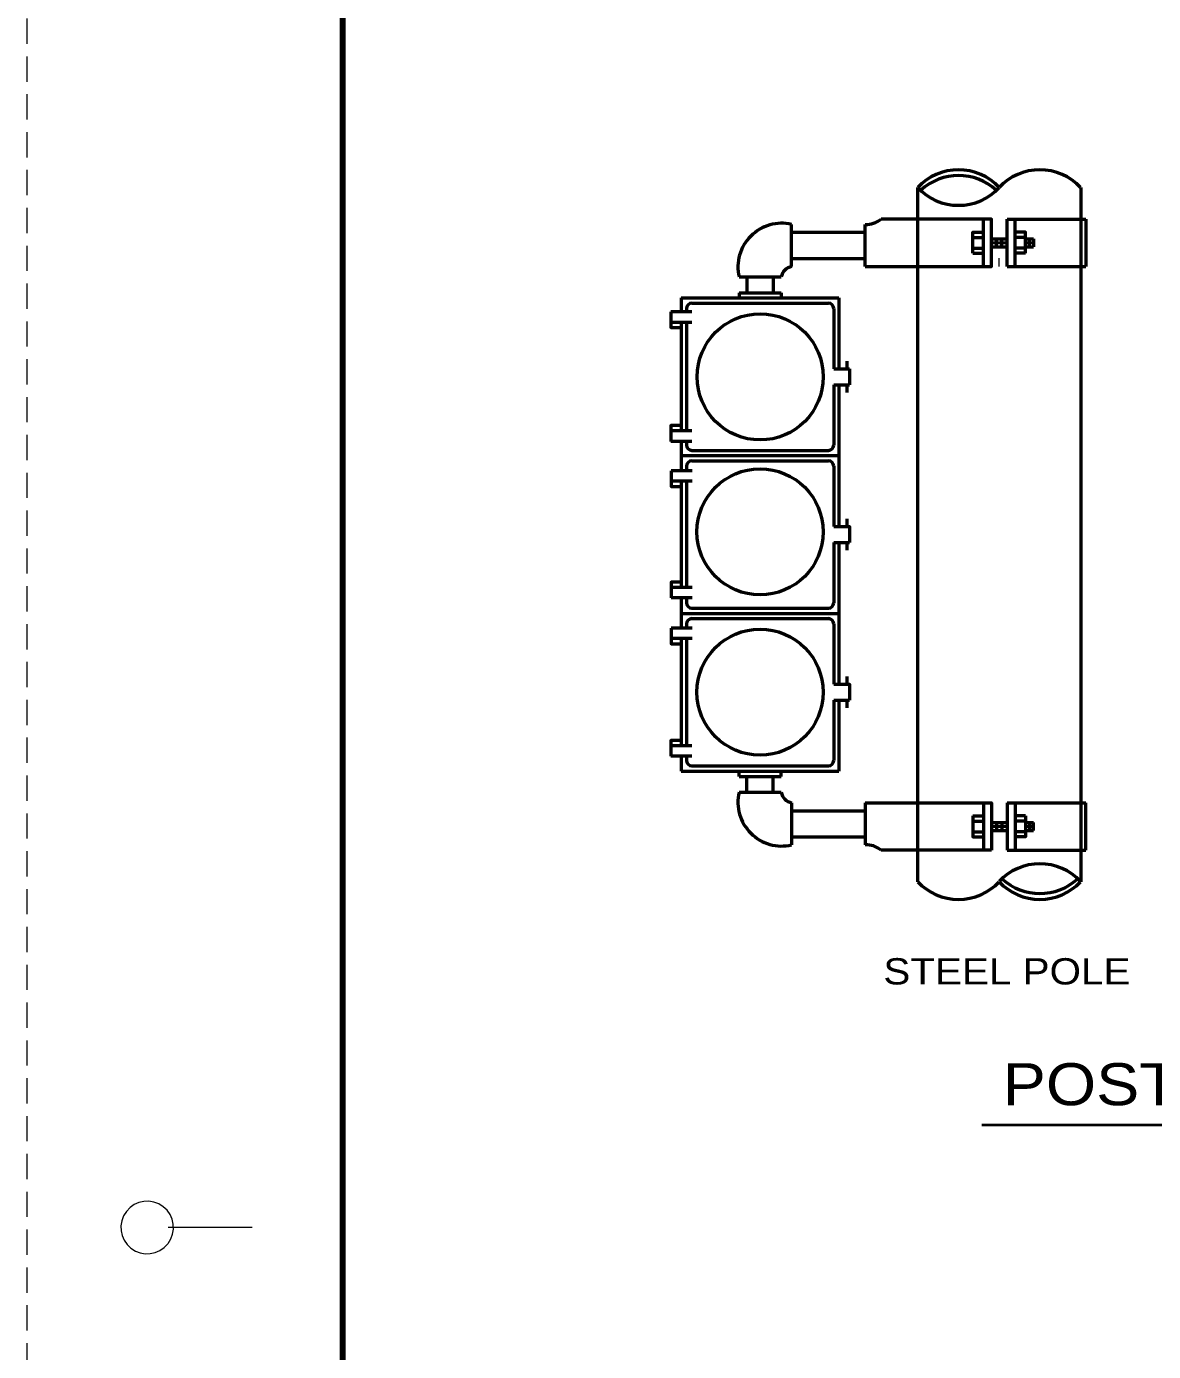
# Model space of a CAD drawing. Extents: x -286 to 394, y -156 to 284.
# Drawn here: x -286.4 to -179.2, y -29.5 to 96.5 of the extents above; entities that cross this region are included whole.
import ezdxf
from ezdxf.enums import TextEntityAlignment as Align

# ---------------------------------------------------------------- set-up
doc = ezdxf.new("R2010")
doc.units = 0
doc.header["$LTSCALE"] = 0.8
doc.linetypes.add('MEDIUM_DASHED', pattern=[4.5, 3, -1.5])
doc.layers.add('1', color=7, linetype='Continuous', lineweight=53)
doc.layers.add('61', color=7, linetype='Continuous', lineweight=35)

msp = doc.modelspace()

# ---------------------------------------------------------------- linework, layer by layer
at = {"layer": '1', "linetype": 'MEDIUM_DASHED', "lineweight": 13}
msp.add_line((-286.3491, 284.4627), (-286.4091, -155.5772), dxfattribs=at)
at = {"layer": '1'}
for p, q in [((-201.6205, 15.1619), (-201.6205, 81.1877)), ((-186.1205, 81.1877), (-186.1205, 15.1619)), ((-195.3705, 73.6877), (-195.3705, 78.1877)), ((-193.1205, 73.6877), (-193.1205, 78.1877)), ((-193.1205, 78.1877), (-185.6205, 78.1877)), ((-192.3705, 73.6877), (-192.3705, 78.1877)), ((-185.6205, 78.1877), (-185.6205, 73.6877)), ((-213.6205, 73.6877), (-213.6205, 77.6877)), ((-213.6205, 76.9377), (-206.6205, 76.9377)), ((-206.6205, 73.6877), (-206.6205, 77.6877)), ((-196.3705, 76.4377), (-195.3705, 76.4377)), ((-194.6205, 76.3127), (-193.1205, 76.3127)), ((-194.3705, 75.8127), (-194.3705, 76.0627)), ((-194.1205, 75.5627), (-194.1205, 76.3127)), ((-193.8705, 75.8127), (-193.8705, 76.0627)), ((-193.6205, 75.5627), (-193.6205, 76.3127)), ((-193.3705, 75.8127), (-193.3705, 76.0627)), ((-191.3735, 76.4377), (-192.3735, 76.4377)), ((-191.186, 76.0627), (-191.186, 75.8127)), ((-190.9985, 75.5627), (-190.9985, 76.3127)), ((-190.811, 76.0627), (-190.811, 75.8127)), ((-190.6235, 76.3127), (-190.6235, 75.5627)), ((-213.6205, 74.4377), (-206.6205, 74.4377)), ((-196.3705, 75.4377), (-195.3705, 75.4377)), ((-196.3705, 74.9377), (-195.3705, 74.9377)), ((-194.6205, 75.5627), (-193.1205, 75.5627)), ((-191.3735, 75.4377), (-192.3735, 75.4377)), ((-191.3735, 74.9377), (-192.3735, 74.9377)), ((-191.3735, 75.5627), (-190.6235, 75.5627)), ((-193.1205, 73.6877), (-185.6205, 73.6877)), ((-218.6205, 72.6877), (-214.6205, 72.6877)), ((-217.8705, 72.6877), (-217.8705, 71.1877)), ((-215.3705, 72.6877), (-215.3705, 71.1877)), ((-224.1205, 70.6877), (-209.1205, 70.6877)), ((-224.1205, 70.6877), (-224.1205, 69.3678)), ((-218.6205, 71.1877), (-214.6205, 71.1877)), ((-218.6205, 71.1877), (-218.6205, 70.6877)), ((-214.6205, 71.1877), (-214.6205, 70.6877)), ((-209.1205, 70.6877), (-209.1205, 63.9378)), ((-223.1205, 69.3678), (-225.1205, 69.3678)), ((-223.6205, 69.6877), (-223.6205, 69.3678)), ((-223.1205, 70.1877), (-210.1205, 70.1877)), ((-209.6205, 69.6877), (-209.6205, 63.9378)), ((-223.1205, 68.3678), (-225.1205, 68.3678)), ((-224.1205, 68.3678), (-224.1205, 58.0468)), ((-223.6205, 68.3678), (-223.6205, 58.0468)), ((-208.3705, 64.6877), (-208.3705, 63.9378)), ((-209.6205, 63.9378), (-208.1205, 63.9378)), ((-208.1205, 63.9378), (-208.1205, 62.4378)), ((-209.6205, 62.4378), (-209.6205, 56.6878)), ((-209.6205, 62.4378), (-208.1205, 62.4378)), ((-209.1205, 62.4378), (-209.1205, 48.9378)), ((-208.3705, 62.4378), (-208.3705, 61.6878)), ((-223.1205, 58.0468), (-225.1205, 58.0468)), ((-223.1205, 57.0468), (-225.1205, 57.0468)), ((-224.1205, 57.0468), (-224.1205, 54.2587)), ((-223.6205, 57.0468), (-223.6205, 56.6878)), ((-224.1205, 55.6878), (-209.1205, 55.6878)), ((-223.1205, 56.1878), (-210.1205, 56.1878)), ((-223.0789, 54.2587), (-225.0789, 54.2587)), ((-223.6205, 54.6878), (-223.6205, 54.2587)), ((-223.1205, 55.1878), (-210.1205, 55.1878)), ((-209.6205, 54.6878), (-209.6205, 48.9378)), ((-223.0789, 53.2587), (-225.0789, 53.2587)), ((-224.1205, 53.2587), (-224.1205, 43.1597)), ((-223.6205, 53.2587), (-223.6205, 43.1597)), ((-208.3705, 49.6878), (-208.3705, 48.9378)), ((-209.6205, 47.4378), (-208.1205, 47.4378)), ((-209.6205, 47.4378), (-209.6205, 41.6878)), ((-209.1205, 47.4378), (-209.1205, 33.9378)), ((-208.3705, 47.4378), (-208.3705, 46.6878)), ((-223.0789, 43.1597), (-225.0789, 43.1597)), ((-223.0789, 42.1597), (-225.0789, 42.1597)), ((-224.1205, 42.1597), (-224.1205, 39.2854)), ((-223.6205, 42.1597), (-223.6205, 41.6878)), ((-224.1205, 40.6878), (-209.1205, 40.6878)), ((-223.1205, 41.1878), (-210.1205, 41.1878)), ((-223.0956, 39.2854), (-225.0956, 39.2854)), ((-223.6205, 39.6878), (-223.6205, 39.2854)), ((-223.1205, 40.1878), (-210.1205, 40.1878)), ((-209.6205, 39.6878), (-209.6205, 33.9378)), ((-223.0956, 38.2854), (-225.0956, 38.2854)), ((-224.1205, 38.2854), (-224.1205, 28.0879)), ((-223.6205, 38.2854), (-223.6205, 28.0879)), ((-208.3705, 34.6878), (-208.3705, 33.9378)), ((-209.6205, 32.4378), (-208.1205, 32.4378)), ((-209.6205, 32.4378), (-209.6205, 26.6877)), ((-209.1205, 32.4378), (-209.1205, 25.6877)), ((-208.3705, 32.4378), (-208.3705, 31.6877)), ((-223.1219, 28.0879), (-225.1219, 28.0879)), ((-223.1219, 27.0879), (-225.1219, 27.0879)), ((-224.1205, 27.0879), (-224.1205, 25.6877)), ((-223.6205, 27.0879), (-223.6205, 26.6877)), ((-224.1205, 25.6877), (-209.1205, 25.6877)), ((-223.1205, 26.1877), (-210.1205, 26.1877)), ((-218.6205, 25.1619), (-218.6205, 25.6619)), ((-214.6205, 25.1619), (-214.6205, 25.6619)), ((-218.6205, 25.1619), (-214.6205, 25.1619)), ((-217.8705, 23.6619), (-217.8705, 25.1619)), ((-215.3705, 23.6619), (-215.3705, 25.1619)), ((-218.6205, 23.6619), (-214.6205, 23.6619)), ((-213.6205, 22.6619), (-213.6205, 18.6619)), ((-213.6205, 21.9119), (-206.6205, 21.9119)), ((-206.6205, 22.6619), (-206.6205, 18.6619)), ((-195.3705, 22.6619), (-195.3705, 18.1619)), ((-193.1205, 22.6619), (-193.1205, 18.1619)), ((-193.1205, 22.6619), (-185.6205, 22.6619)), ((-192.3705, 22.6619), (-192.3705, 18.1619)), ((-185.6205, 18.1619), (-185.6205, 22.6619)), ((-196.3705, 21.4119), (-195.3705, 21.4119)), ((-196.3705, 20.9119), (-195.3705, 20.9119)), ((-194.6205, 20.7869), (-193.1205, 20.7869)), ((-194.3705, 20.5369), (-194.3705, 20.2869)), ((-194.1205, 20.7869), (-194.1205, 20.0369)), ((-193.8705, 20.5369), (-193.8705, 20.2869)), ((-193.6205, 20.7869), (-193.6205, 20.0369)), ((-193.3705, 20.5369), (-193.3705, 20.2869)), ((-191.3735, 21.4119), (-192.3735, 21.4119)), ((-191.3735, 20.9119), (-192.3735, 20.9119)), ((-191.3735, 20.7869), (-190.6235, 20.7869)), ((-191.186, 20.2869), (-191.186, 20.5369)), ((-190.9985, 20.7869), (-190.9985, 20.0369)), ((-190.811, 20.2869), (-190.811, 20.5369)), ((-190.6235, 20.0369), (-190.6235, 20.7869)), ((-213.6205, 19.4119), (-206.6205, 19.4119)), ((-196.3705, 19.9119), (-195.3705, 19.9119)), ((-194.6205, 20.0369), (-193.1205, 20.0369)), ((-191.3735, 19.9119), (-192.3735, 19.9119)), ((-191.3735, 20.0369), (-190.6235, 20.0369)), ((-194.6205, 18.1619), (-205.1205, 18.1619)), ((-193.1205, 18.1619), (-185.6205, 18.1619))]:
    msp.add_line(p, q, dxfattribs=at)
at = {"layer": '1', "lineweight": 13}
msp.add_line((-193.8705, 73.6877), (-193.8705, 74.4736), dxfattribs=at)
at = {"layer": '1', "lineweight": 40}
msp.add_line((-195.529, -7.9817), (-123.0741, -7.9817), dxfattribs=at)
at = {"layer": '1'}
for points in [[(-206.6205, 73.6877), (-194.6205, 73.6877), (-194.6205, 78.1877), (-205.1205, 78.1877)], [(-196.3705, 74.9377), (-196.3705, 76.9377), (-195.3705, 76.9377)], [(-191.3735, 74.9377), (-191.3735, 76.9377), (-192.3735, 76.9377)], [(-191.3735, 76.3127), (-190.9985, 76.3127), (-190.6235, 76.3127)], [(-225.1205, 69.3678), (-225.1205, 67.8678), (-224.1205, 67.8678)], [(-224.1205, 58.5468), (-225.1205, 58.5468), (-225.1205, 57.0468)], [(-225.0789, 54.2587), (-225.0789, 52.7587), (-224.0789, 52.7587)], [(-209.6205, 48.9378), (-208.1205, 48.9378), (-208.1205, 47.4378)], [(-224.0789, 43.6597), (-225.0789, 43.6597), (-225.0789, 42.1597)], [(-225.0956, 39.2854), (-225.0956, 37.7854), (-224.0956, 37.7854)], [(-209.6205, 33.9378), (-208.1205, 33.9378), (-208.1205, 32.4378)], [(-224.1219, 28.5879), (-225.1219, 28.5879), (-225.1219, 27.0879)], [(-206.6205, 22.6619), (-194.6205, 22.6619), (-194.6205, 18.1619)], [(-196.3705, 21.4119), (-196.3705, 19.4119), (-195.3705, 19.4119)], [(-191.3735, 21.4119), (-191.3735, 19.4119), (-192.3735, 19.4119)]]:
    msp.add_lwpolyline(points, dxfattribs=at)
for centre in [(-216.6142, 63.1818), (-216.6257, 48.4382), (-216.6261, 33.1901)]:
    msp.add_circle(centre, 6, dxfattribs=at)
for centre, radius, start, end in [((-197.7455, 77.5927), 5.2962, 42.97503, 137.02497), ((-197.7455, 77.0371), 5.2962, 47.11243, 132.88757), ((-190.0073, 77.5927), 5.2962, 42.97503, 137.02497), ((-197.7455, 84.7981), 5.2962, 222.97503, 317.02497), ((-206.4918, 79.8017), 2.1178, 266.51631, 310.35359), ((-214.565, 73.6322), 4.164, 76.89015, 193.10985), ((-213.337, 72.4042), 1.3145, 102.45679, 167.54321), ((-223.1205, 69.6877), 0.5, 90, 180), ((-210.1205, 69.6877), 0.5, 0, 90), ((-223.1205, 56.6878), 0.5, 180, 270), ((-210.1205, 56.6878), 0.5, 270, 0), ((-223.1205, 54.6878), 0.5, 90, 180), ((-210.1205, 54.6878), 0.5, 0, 90), ((-223.1205, 41.6878), 0.5, 180, 270), ((-210.1205, 41.6878), 0.5, 270, 0), ((-223.1205, 39.6878), 0.5, 90, 180), ((-210.1205, 39.6878), 0.5, 0, 90), ((-223.1205, 26.6877), 0.5, 180, 270), ((-210.1205, 26.6877), 0.5, 270, 0), ((-214.565, 22.7174), 4.164, 166.89015, 283.10985), ((-213.337, 23.9455), 1.3145, 192.45679, 257.54321), ((-206.4918, 16.548), 2.1178, 49.64641, 93.48369), ((-190.0073, 11.5669), 5.2962, 42.97503, 137.02497), ((-197.7455, 18.7723), 5.2962, 222.97503, 317.02497), ((-190.0073, 18.7723), 5.2962, 222.97503, 317.02497), ((-190.0073, 19.3279), 5.2962, 227.11243, 312.88757)]:
    msp.add_arc(centre, radius, start, end, dxfattribs=at)
at = {"layer": '61', "lineweight": 13}
msp.add_line((-272.9291, -17.7172), (-264.9291, -17.7172), dxfattribs=at)
at = {"layer": '61', "lineweight": 158}
msp.add_lwpolyline([(382.6909, 274.4627), (-256.3491, 274.4627), (-256.3491, -145.5572)], dxfattribs=at)
at = {"layer": '61', "lineweight": 13}
msp.add_arc((-274.9313, -17.736), 2.5, 322.67175, 321.71615, dxfattribs=at)

# ---------------------------------------------------------------- texts
at = {"layer": '1', "width": 1.15}
for s, height, p in [('STEEL POLE', 2.5, (-193.1438, 5.3828)), ('POST MOUNT METHOD', 4, (-158.8555, -6.1044))]:
    msp.add_text(s, height=height, dxfattribs=at).set_placement(p, align=Align.CENTER)

doc.saveas('drawing.dxf')
